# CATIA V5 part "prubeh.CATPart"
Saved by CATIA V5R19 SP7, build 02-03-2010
Part number: Part3
Bounding box of the stored display mesh (mm): x 0 to 31.745, y 0 to 19.086, z 0 to 0
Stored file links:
  D:\CATIA FÓRUM\prubeh.CATPart
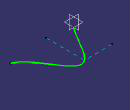
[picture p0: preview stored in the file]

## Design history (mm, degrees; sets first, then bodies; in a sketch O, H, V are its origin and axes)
Parameters
  x = 13
  y = 18.1426 {= length(Line1 ) / 1mm}
Set1
  Sketch1 on xy-plane, origin (0, 0, 0), H (1, 0, 0), V (0, 1, 0)
    spline S1 through (1.8968, 1.725) (7.2152, 10.0257) (15.464, 19.0859) (23.1702, 10.948) (31.7447, 1.8335)
  Point1: (13 {= x * 1mm}, 0, 0)
  Line1: type Normal, LineFirstUpto zx-plane, LineSecondUpto Sketch1, RefPoint Point1, Start 0, End 30
  Line2: type PtDir, LineFirstUpto yz-plane, LineSecondUpto Line1, RefPoint vertex of Line1, Direction yz-plane, Start 0, End 30
Body1 (main body)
